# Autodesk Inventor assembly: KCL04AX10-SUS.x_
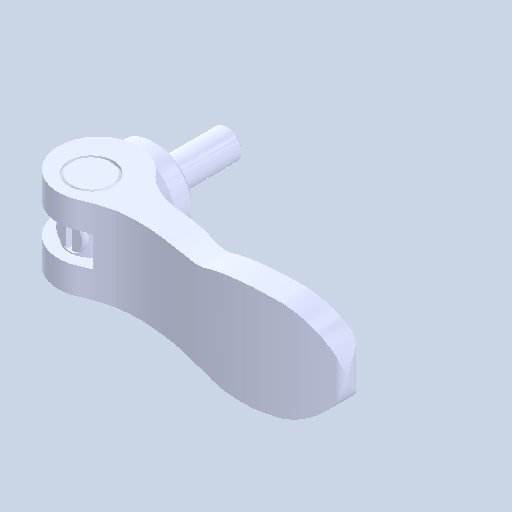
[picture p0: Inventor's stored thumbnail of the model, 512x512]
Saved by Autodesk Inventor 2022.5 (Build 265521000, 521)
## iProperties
Created: 2024-08
Part Number: KCL04AX10-SUS.x_
Document SubType Name: Assembly
Designer: ImaoCorp
Author: ImaoCorp
Sending System: SOLIDWORKS 2022-2022290
MC: AMD64
MC_MODEL: Intel64 Family 6 Model 60 Stepping 3, GenuineIntel
OS: Windows_NT
FRU: Parasolid Version 33.1, build 260,  4-25-2022
FORMAT: text
GUISE: transmit
KEY: FILEKCL04AX10-SUS.x_t
DATE: Thu Aug 29 10:47:25 2024
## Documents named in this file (5)
- Y:\5.更新分\2024年対応\1001_KCL\データ\kcl04ax10-sus\KCL04AX10-SUS.x_.iam
- Y:\5.更新分\2024年対応\1001_KCL\データ\kcl04ax10-sus\KCL04AX10-SUS_01.ipt
- Y:\5.更新分\2024年対応\1001_KCL\データ\kcl04ax10-sus\KCL04AX10-SUS_02.ipt
- Y:\5.更新分\2024年対応\1001_KCL\データ\kcl04ax10-sus\KCL04AX10-SUS_03.ipt
- Y:\5.更新分\2024年対応\1001_KCL\データ\kcl04ax10-sus\KCL04AX10-SUS_04.ipt
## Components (4 placed, 4 different names)
1. KCL04AX10-SUS_01
2. KCL04AX10-SUS_02
3. KCL04AX10-SUS_03
4. KCL04AX10-SUS_04
